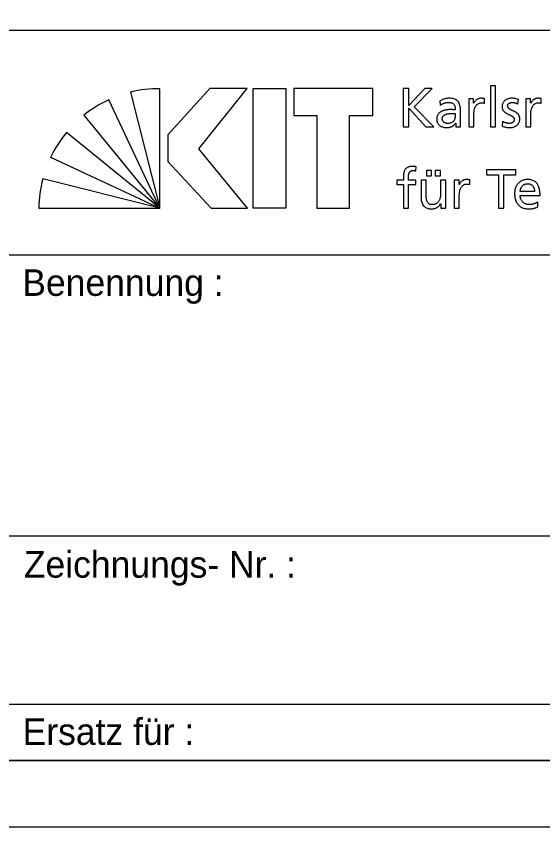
# Model space of a CAD drawing. Extents: x 0 to 59.5, y 0 to 42.1.
# Drawn here: x 55.033 to 57.016, y 0 to 3.052 of the extents above; entities that cross this region are included whole.
import ezdxf

# ---------------------------------------------------------------- set-up
doc = ezdxf.new("R2010")
doc.units = 0
doc.layers.add('90_Plankopf', color=7, linetype='Continuous')

msp = doc.modelspace()

# ---------------------------------------------------------------- linework, layer by layer
at = {"layer": '90_Plankopf'}
for p, q in [((50.306, 2.9995), (59.2, 2.9995)), ((50.306, 2.9995), (59.2, 2.9995)), ((55.574, 2.3293), (55.574, 2.7792)), ((56.4905, 2.7793), (56.4905, 2.6353)), ((55.4637, 2.7666), (55.574, 2.3293)), ((55.574, 2.3293), (55.3817, 2.7376)), ((56.629, 2.7331), (56.63, 2.7166)), ((56.7963, 2.7242), (56.7963, 2.7416)), ((56.9228, 2.722), (56.9245, 2.7389)), ((57.0106, 2.7242), (57.0106, 2.7416)), ((56.7059, 2.6559), (56.7059, 2.6995)), ((55.2872, 2.6793), (55.574, 2.3293)), ((56.6865, 2.6854), (56.6865, 2.6761)), ((56.8649, 2.6559), (56.8638, 2.6386)), ((56.4905, 2.6353), (56.5111, 2.6353)), ((56.5753, 2.6353), (56.6054, 2.6353)), ((55.574, 2.3293), (55.2217, 2.6143)), ((55.162, 2.5207), (55.574, 2.3293)), ((56.5387, 2.4696), (56.5395, 2.4853)), ((55.574, 2.3293), (55.1329, 2.4394)), ((56.7413, 2.4182), (56.7413, 2.4356)), ((56.9853, 2.392), (56.9308, 2.392)), ((56.9308, 2.3776), (57.0059, 2.3776)), ((56.9979, 2.3337), (56.9979, 2.353)), ((55.1182, 2.3293), (55.574, 2.3293)), ((55.0001, 2.1535), (59.2, 2.1535)), ((55.0001, 1.096), (59.2, 1.096)), ((55.0001, 0.4615), (59.2, 0.4615)), ((59.2, 0.25), (50.306, 0.25)), ((50.89, 0.25), (59.2, 0.25)), ((50.89, 0.25), (59.2, 0.25))]:
    msp.add_line(p, q, dxfattribs=at)
for points in [[(0, 0), (59.45, 0), (59.45, 42.05), (0, 42.05)], [(1.25, 0.25), (59.2, 0.25), (59.2, 41.8), (1.25, 41.8)], [(55.9033, 2.7793), (55.7618, 2.7793), (55.6036, 2.6049), (55.6036, 2.5046), (55.7669, 2.3293), (55.9042, 2.3293), (55.7211, 2.5531)], [(56.0485, 2.7793), (56.0485, 2.3293), (55.9251, 2.3293), (55.9251, 2.7793)], [(56.0781, 2.7793), (56.0781, 2.678), (56.1651, 2.678), (56.1651, 2.3293), (56.2885, 2.3293), (56.2885, 2.678), (56.3755, 2.678), (56.3755, 2.7793)]]:
    msp.add_lwpolyline(points, close=True, dxfattribs=at)
for points in [[(56.6054, 2.6353), (56.5324, 2.7112), (56.6, 2.7793), (56.5726, 2.7793), (56.5111, 2.716), (56.5111, 2.7793), (56.4905, 2.7793)], [(56.819, 2.6353), (56.8384, 2.6353), (56.8384, 2.79), (56.819, 2.79), (56.819, 2.6353)], [(56.7561, 2.7242), (56.7557, 2.7242), (56.7557, 2.7405), (56.7375, 2.7405), (56.7375, 2.6353), (56.7569, 2.6353), (56.7569, 2.6832)], [(56.9703, 2.7242), (56.9699, 2.7242), (56.9699, 2.7405), (56.9518, 2.7405), (56.9518, 2.6353), (56.9712, 2.6353), (56.9712, 2.6832)], [(56.5111, 2.6353), (56.5111, 2.7059), (56.5753, 2.6353)], [(56.6882, 2.6489), (56.6886, 2.6489), (56.6886, 2.6353), (56.7067, 2.6353)], [(56.8495, 2.3293), (56.8701, 2.3293), (56.8701, 2.4552), (56.9149, 2.4552), (56.9149, 2.4733), (56.8047, 2.4733), (56.8047, 2.4552), (56.8495, 2.4552), (56.8495, 2.3293)], [(56.4912, 2.4443), (56.4912, 2.4346), (56.4665, 2.4346), (56.4665, 2.4189), (56.4912, 2.4189), (56.4912, 2.3293), (56.5106, 2.3293), (56.5106, 2.4189), (56.5385, 2.4189), (56.5385, 2.4346), (56.5106, 2.4346), (56.5106, 2.4459)], [(56.5777, 2.4713), (56.5777, 2.4506), (56.5971, 2.4506), (56.5971, 2.4713), (56.5777, 2.4713)], [(56.6115, 2.4713), (56.6115, 2.4506), (56.6309, 2.4506), (56.6309, 2.4713), (56.6115, 2.4713)], [(56.5771, 2.3801), (56.5771, 2.4346), (56.5577, 2.4346), (56.5577, 2.372)], [(56.6507, 2.3293), (56.6507, 2.4346), (56.6313, 2.4346), (56.6313, 2.3859)], [(56.7011, 2.4182), (56.7007, 2.4182), (56.7007, 2.4346), (56.6825, 2.4346), (56.6825, 2.3293), (56.7019, 2.3293), (56.7019, 2.3772)], [(56.6316, 2.346), (56.632, 2.346), (56.632, 2.3293), (56.6507, 2.3293)]]:
    msp.add_lwpolyline(points, dxfattribs=at)
for centre, start, end in [((55.5724, 2.3028), 89.8053, 103.1895), ((55.5831, 2.3059), 115.0126, 128.3968), ((55.5908, 2.3131), 140.7898, 154.174), ((55.5946, 2.3219), 165.7222, 179.1064)]:
    msp.add_arc(centre, 0.4764, start, end, dxfattribs=at)
for points in [[(56.7059, 2.6995), (56.706, 2.709), (56.7045, 2.717), (56.7017, 2.7235), (56.6988, 2.73), (56.6942, 2.7348), (56.688, 2.7381), (56.6817, 2.7413), (56.6736, 2.743), (56.6636, 2.743), (56.6569, 2.743), (56.6507, 2.742), (56.6449, 2.7402), (56.6391, 2.7384), (56.6338, 2.7361), (56.629, 2.7331)], [(56.63, 2.7166), (56.6326, 2.7188), (56.6356, 2.7207), (56.639, 2.7223), (56.6423, 2.7239), (56.6458, 2.7251), (56.6495, 2.726), (56.6532, 2.7269), (56.6568, 2.7273), (56.6605, 2.7273), (56.667, 2.7273), (56.6721, 2.7263), (56.6759, 2.7243), (56.6797, 2.7222), (56.6824, 2.7191), (56.6841, 2.7151), (56.6858, 2.711), (56.6865, 2.7059), (56.6865, 2.6999)], [(56.7963, 2.7416), (56.795, 2.7418), (56.7937, 2.7421), (56.7925, 2.7423), (56.7912, 2.7425), (56.7899, 2.7427), (56.7885, 2.7428), (56.7871, 2.7429), (56.7854, 2.743), (56.7835, 2.743), (56.7798, 2.743), (56.7761, 2.7422), (56.7726, 2.7406), (56.7691, 2.739), (56.7659, 2.7368), (56.763, 2.7339), (56.7601, 2.7311), (56.7578, 2.7279), (56.7561, 2.7242)], [(56.7569, 2.6832), (56.7569, 2.692), (56.7581, 2.6996), (56.7605, 2.706), (56.7629, 2.7124), (56.7662, 2.7174), (56.7705, 2.7208), (56.7747, 2.7243), (56.7798, 2.726), (56.7856, 2.7261), (56.7873, 2.7261), (56.789, 2.726), (56.7909, 2.7257), (56.7927, 2.7254), (56.7945, 2.7249), (56.7963, 2.7242)], [(56.9245, 2.7389), (56.9207, 2.74), (56.9169, 2.741), (56.913, 2.7418), (56.9091, 2.7426), (56.9049, 2.743), (56.9004, 2.743), (56.8951, 2.743), (56.8903, 2.7423), (56.8858, 2.741), (56.8813, 2.7397), (56.8774, 2.7377), (56.874, 2.735), (56.8706, 2.7323), (56.868, 2.729), (56.8661, 2.7249), (56.8642, 2.7208), (56.8632, 2.7161), (56.8632, 2.7106), (56.8632, 2.7064), (56.8641, 2.7028), (56.8658, 2.6997), (56.8674, 2.6966), (56.8695, 2.694), (56.8723, 2.6917), (56.875, 2.6895), (56.8779, 2.6875), (56.8812, 2.6857), (56.8844, 2.684), (56.8876, 2.6824), (56.8909, 2.6809), (56.8941, 2.6793), (56.8971, 2.6777), (56.8998, 2.6761), (56.9025, 2.6745), (56.9047, 2.6727), (56.9063, 2.6706), (56.9079, 2.6686), (56.9088, 2.6663), (56.9088, 2.6636), (56.9088, 2.6607), (56.9082, 2.6584), (56.907, 2.6564), (56.9058, 2.6545), (56.9042, 2.6529), (56.9022, 2.6518), (56.9003, 2.6506), (56.8982, 2.6498), (56.8959, 2.6493), (56.8935, 2.6487), (56.8912, 2.6485), (56.889, 2.6485), (56.8871, 2.6485), (56.8847, 2.6488), (56.882, 2.6493), (56.8792, 2.6499), (56.8763, 2.6507), (56.8733, 2.6518), (56.8703, 2.6529), (56.8675, 2.6543), (56.8649, 2.6559)], [(56.8638, 2.6386), (56.8683, 2.6363), (56.873, 2.6347), (56.8779, 2.6339), (56.8828, 2.6331), (56.8877, 2.6327), (56.8927, 2.6328), (56.8975, 2.6328), (56.902, 2.6335), (56.9064, 2.6348), (56.9107, 2.6361), (56.9147, 2.6381), (56.9181, 2.6408), (56.9216, 2.6435), (56.9243, 2.6469), (56.9264, 2.651), (56.9284, 2.6551), (56.9294, 2.66), (56.9295, 2.6656), (56.9294, 2.6704), (56.9286, 2.6745), (56.9269, 2.6778), (56.9253, 2.6811), (56.9231, 2.684), (56.9204, 2.6863), (56.9177, 2.6886), (56.9147, 2.6906), (56.9115, 2.6922), (56.9083, 2.6939), (56.905, 2.6954), (56.9018, 2.6968), (56.8986, 2.6983), (56.8956, 2.6998), (56.8929, 2.7013), (56.8902, 2.7029), (56.888, 2.7047), (56.8864, 2.7068), (56.8847, 2.7089), (56.8839, 2.7115), (56.8838, 2.7145), (56.8839, 2.7174), (56.8848, 2.7198), (56.8865, 2.7217), (56.8882, 2.7236), (56.8904, 2.725), (56.8932, 2.7259), (56.896, 2.7269), (56.8991, 2.7273), (56.9024, 2.7273), (56.9036, 2.7273), (56.9051, 2.7271), (56.9069, 2.7269), (56.9088, 2.7266), (56.9107, 2.7261), (56.9127, 2.7256), (56.9148, 2.7251), (56.9167, 2.7246), (56.9185, 2.7239), (56.9203, 2.7233), (56.9217, 2.7226), (56.9228, 2.722)], [(57.0106, 2.7416), (57.0092, 2.7418), (57.0079, 2.7421), (57.0067, 2.7423), (57.0055, 2.7425), (57.0041, 2.7427), (57.0027, 2.7428), (57.0013, 2.7429), (56.9997, 2.743), (56.9978, 2.743), (56.994, 2.743), (56.9904, 2.7422), (56.9868, 2.7406), (56.9833, 2.739), (56.9801, 2.7368), (56.9773, 2.7339), (56.9744, 2.7311), (56.9721, 2.7279), (56.9703, 2.7242)], [(56.9712, 2.6832), (56.9712, 2.692), (56.9724, 2.6996), (56.9747, 2.706), (56.9771, 2.7124), (56.9804, 2.7174), (56.9847, 2.7208), (56.989, 2.7243), (56.994, 2.726), (56.9998, 2.7261), (57.0015, 2.7261), (57.0033, 2.726), (57.0051, 2.7257), (57.007, 2.7254), (57.0088, 2.7249), (57.0106, 2.7242)], [(56.6865, 2.6999), (56.684, 2.7), (56.6817, 2.7001), (56.6795, 2.7001), (56.6773, 2.7002), (56.6751, 2.7003), (56.6729, 2.7003), (56.6708, 2.7003), (56.6684, 2.7003), (56.6659, 2.7003), (56.6618, 2.7003), (56.6576, 2.6999), (56.6531, 2.6992), (56.6487, 2.6985), (56.6443, 2.6973), (56.64, 2.6957), (56.6358, 2.6941), (56.6319, 2.6919), (56.6284, 2.6892), (56.625, 2.6866), (56.6222, 2.6833), (56.6201, 2.6794), (56.6181, 2.6755), (56.6171, 2.6709), (56.617, 2.6656), (56.6171, 2.658), (56.6187, 2.6518), (56.6219, 2.6469), (56.6252, 2.6421), (56.6297, 2.6385), (56.6355, 2.6362), (56.6413, 2.6339), (56.6479, 2.6328), (56.6556, 2.6328), (56.66, 2.6328), (56.664, 2.6334), (56.6675, 2.6344), (56.671, 2.6355), (56.6741, 2.6368), (56.6768, 2.6384), (56.6795, 2.6401), (56.6818, 2.6419), (56.6837, 2.6437), (56.6855, 2.6455), (56.687, 2.6472), (56.6882, 2.6489)], [(56.6865, 2.6761), (56.6865, 2.6709), (56.6854, 2.6661), (56.6832, 2.662), (56.681, 2.6578), (56.6777, 2.6546), (56.6733, 2.6522), (56.669, 2.6498), (56.6636, 2.6485), (56.6572, 2.6485), (56.655, 2.6485), (56.6527, 2.6489), (56.6504, 2.6496), (56.6481, 2.6503), (56.646, 2.6514), (56.6441, 2.6529), (56.6422, 2.6543), (56.6406, 2.6561), (56.6394, 2.6582), (56.6383, 2.6604), (56.6377, 2.6628), (56.6376, 2.6656), (56.6377, 2.6693), (56.6386, 2.6724), (56.6404, 2.6749), (56.6422, 2.6773), (56.6446, 2.6793), (56.6475, 2.6807), (56.6503, 2.6822), (56.6534, 2.6833), (56.6567, 2.6841), (56.66, 2.6848), (56.6632, 2.6853), (56.6663, 2.6855), (56.6694, 2.6858), (56.672, 2.6859), (56.6741, 2.6858), (56.6762, 2.6858), (56.6783, 2.6858), (56.6803, 2.6856), (56.6824, 2.6855), (56.6845, 2.6855), (56.6865, 2.6854)], [(56.7067, 2.6353), (56.7066, 2.6363), (56.7065, 2.6377), (56.7063, 2.6393), (56.7062, 2.6411), (56.7061, 2.6433), (56.7061, 2.646), (56.706, 2.6486), (56.7059, 2.652), (56.7059, 2.6559)], [(56.5395, 2.4853), (56.5375, 2.4856), (56.5355, 2.4859), (56.5334, 2.4862), (56.5312, 2.4864), (56.529, 2.4866), (56.5265, 2.4866), (56.5194, 2.4865), (56.5135, 2.4855), (56.5089, 2.4836), (56.5043, 2.4816), (56.5007, 2.4787), (56.4981, 2.475), (56.4955, 2.4713), (56.4937, 2.4668), (56.4927, 2.4616), (56.4917, 2.4565), (56.4912, 2.4507), (56.4912, 2.4443)], [(56.5106, 2.4459), (56.5106, 2.4495), (56.5108, 2.4528), (56.5112, 2.4558), (56.5116, 2.4588), (56.5125, 2.4615), (56.5137, 2.4637), (56.515, 2.466), (56.5169, 2.4677), (56.5194, 2.469), (56.5219, 2.4702), (56.5252, 2.4709), (56.5294, 2.4709), (56.5311, 2.4709), (56.5328, 2.4708), (56.5344, 2.4706), (56.5361, 2.4703), (56.5375, 2.47), (56.5387, 2.4696)], [(56.7413, 2.4356), (56.74, 2.4359), (56.7387, 2.4361), (56.7375, 2.4363), (56.7363, 2.4365), (56.7349, 2.4367), (56.7335, 2.4368), (56.7321, 2.437), (56.7304, 2.437), (56.7286, 2.437), (56.7248, 2.437), (56.7212, 2.4362), (56.7176, 2.4346), (56.7141, 2.433), (56.7109, 2.4308), (56.7081, 2.428), (56.7052, 2.4252), (56.7029, 2.4219), (56.7011, 2.4182)], [(56.7019, 2.3772), (56.702, 2.386), (56.7032, 2.3937), (56.7055, 2.4001), (56.7079, 2.4065), (56.7112, 2.4114), (56.7155, 2.4148), (56.7198, 2.4183), (56.7248, 2.4201), (56.7306, 2.4201), (56.7323, 2.4201), (56.7341, 2.42), (56.7359, 2.4197), (56.7378, 2.4195), (56.7396, 2.419), (56.7413, 2.4182)], [(57.0059, 2.3776), (57.006, 2.3861), (57.0052, 2.394), (57.0036, 2.4012), (57.002, 2.4084), (56.9995, 2.4146), (56.9959, 2.42), (56.9923, 2.4254), (56.9875, 2.4295), (56.9815, 2.4325), (56.9756, 2.4355), (56.9682, 2.437), (56.9595, 2.437), (56.952, 2.437), (56.9453, 2.4357), (56.9392, 2.4331), (56.9332, 2.4305), (56.928, 2.4269), (56.9237, 2.4221), (56.9194, 2.4174), (56.916, 2.4118), (56.9137, 2.4052), (56.9114, 2.3988), (56.9102, 2.3916), (56.9102, 2.3838), (56.9102, 2.3752), (56.9113, 2.3674), (56.9134, 2.3604), (56.9156, 2.3535), (56.919, 2.3475), (56.9234, 2.3425), (56.9279, 2.3375), (56.9335, 2.3336), (56.9404, 2.3309), (56.9473, 2.3282), (56.9553, 2.3269), (56.9647, 2.3268), (56.9704, 2.3269), (56.9753, 2.3273), (56.9793, 2.328), (56.9834, 2.3288), (56.9869, 2.3297), (56.9898, 2.3307), (56.9928, 2.3317), (56.9954, 2.3327), (56.9979, 2.3337)], [(56.9308, 2.392), (56.9312, 2.3955), (56.932, 2.3989), (56.9332, 2.4024), (56.9344, 2.4058), (56.9361, 2.4089), (56.9384, 2.4118), (56.9406, 2.4147), (56.9434, 2.417), (56.9469, 2.4187), (56.9503, 2.4204), (56.9543, 2.4213), (56.9591, 2.4213), (56.9633, 2.4213), (56.967, 2.4206), (56.9702, 2.419), (56.9735, 2.4175), (56.9762, 2.4154), (56.9785, 2.4127), (56.9807, 2.4101), (56.9824, 2.4069), (56.9835, 2.4034), (56.9847, 2.3999), (56.9853, 2.3961), (56.9853, 2.392)], [(56.6313, 2.3859), (56.6313, 2.3794), (56.6307, 2.3736), (56.6295, 2.3683), (56.6282, 2.363), (56.6263, 2.3584), (56.6236, 2.3546), (56.621, 2.3507), (56.6177, 2.3478), (56.6137, 2.3457), (56.6096, 2.3436), (56.6049, 2.3426), (56.5994, 2.3425), (56.5938, 2.3429), (56.5893, 2.3444), (56.5861, 2.3473), (56.5828, 2.3501), (56.5805, 2.3542), (56.5791, 2.3597), (56.5777, 2.3651), (56.5771, 2.3719), (56.5771, 2.3801)], [(56.5577, 2.372), (56.5577, 2.3626), (56.5591, 2.3545), (56.5618, 2.3478), (56.5646, 2.341), (56.569, 2.3359), (56.5748, 2.3323), (56.5806, 2.3287), (56.588, 2.3269), (56.5971, 2.3268), (56.602, 2.3269), (56.6068, 2.3276), (56.6113, 2.3291), (56.6158, 2.3307), (56.6198, 2.3329), (56.6233, 2.3357), (56.6268, 2.3386), (56.6296, 2.342), (56.6316, 2.346)], [(56.9979, 2.353), (56.9967, 2.3521), (56.9949, 2.351), (56.9926, 2.3497), (56.9903, 2.3485), (56.9877, 2.3474), (56.9847, 2.3463), (56.9817, 2.3452), (56.9786, 2.3443), (56.9753, 2.3436), (56.972, 2.3429), (56.9687, 2.3426), (56.9655, 2.3425), (56.9608, 2.3426), (56.9565, 2.3434), (56.9523, 2.3451), (56.9482, 2.3468), (56.9445, 2.3492), (56.9413, 2.3523), (56.938, 2.3554), (56.9355, 2.359), (56.9336, 2.3633), (56.9318, 2.3676), (56.9309, 2.3724), (56.9308, 2.3776)]]:
    msp.add_open_spline(points, degree=3, dxfattribs=at)

# ---------------------------------------------------------------- texts
for s, p in [('Benennung :', (55.0557, 1.999)), ('Zeichnungs- Nr. :', (55.0614, 0.9379)), ('Ersatz für :', (55.0569, 0.3084))]:
    msp.add_text(s, height=0.1, dxfattribs=at).set_placement(p)

doc.saveas('drawing.dxf')
